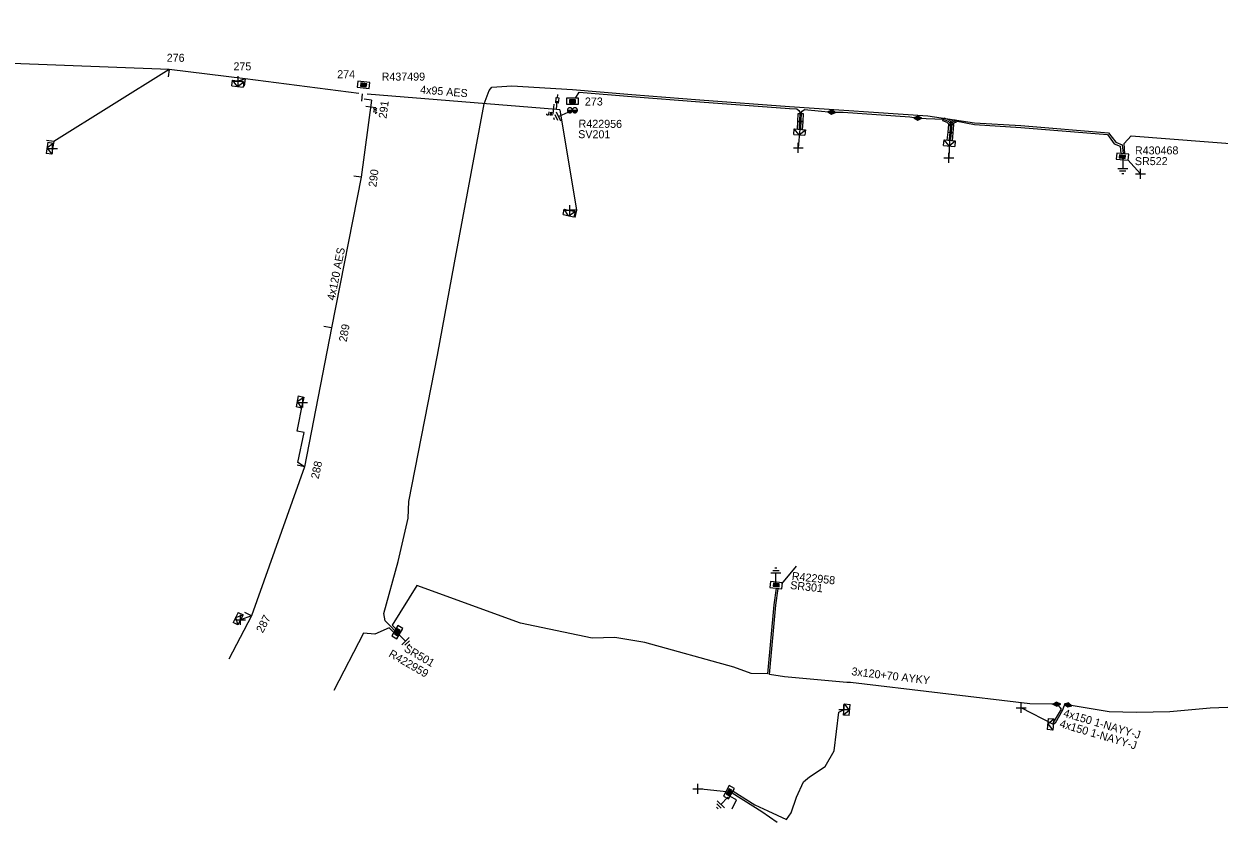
# Model space of a CAD drawing. Extents: x -540247 to -537390, y -1183890 to -1180355.
# Drawn here: x -537955.6 to -537806.3, y -1180715 to -1180615.3 of the extents above; entities that cross this region are included whole.
import ezdxf

# ---------------------------------------------------------------- set-up
doc = ezdxf.new("R2010")
doc.units = 0
for name, color, linetype in [('Vrstva 1', 7, 'Continuous'), ('Vrstva 13', 7, 'Continuous'), ('Vrstva 14', 7, 'Continuous'), ('Vrstva 15', 7, 'Continuous'), ('Vrstva 16', 7, 'Continuous'), ('Vrstva 18', 7, 'Continuous'), ('Vrstva 19', 7, 'Continuous'), ('Vrstva 2', 7, 'Continuous'), ('Vrstva 20', 7, 'Continuous'), ('Vrstva 28', 7, 'Continuous'), ('Vrstva 29', 7, 'Continuous'), ('Vrstva 30', 7, 'Continuous'), ('Vrstva 31', 7, 'Continuous'), ('Vrstva 34', 7, 'Continuous'), ('Vrstva 4', 7, 'Continuous'), ('Vrstva 5', 7, 'Continuous'), ('Vrstva 50', 7, 'Continuous'), ('Vrstva 51', 7, 'Continuous'), ('Vrstva 52', 7, 'Continuous'), ('Vrstva 54', 7, 'Continuous'), ('Vrstva 59', 7, 'Continuous'), ('Vrstva 6', 7, 'Continuous'), ('Vrstva 8', 7, 'Continuous'), ('Vrstva 9', 7, 'Continuous')]:
    doc.layers.add(name, color=color, linetype=linetype)

# ---------------------------------------------------------------- blocks, each defined once
blk = doc.blocks.new('NN450')
at = {"layer": 'Vrstva 2'}
for points in [[(0, 0), (0, 0.07), (-0.01, 0.13), (-0.03, 0.19), (-0.05, 0.25), (-0.08, 0.31), (-0.12, 0.37), (-0.16, 0.42), (-0.21, 0.46), (-0.26, 0.51), (-0.31, 0.54), (-0.37, 0.57), (-0.43, 0.59), (-0.5, 0.61), (-0.56, 0.62), (-0.63, 0.62), (-0.69, 0.62), (-0.75, 0.61), (-0.82, 0.59), (-0.88, 0.57), (-0.94, 0.54), (-0.99, 0.51), (-1.04, 0.46), (-1.09, 0.42), (-1.13, 0.37), (-1.17, 0.31), (-1.2, 0.25), (-1.22, 0.19), (-1.24, 0.13), (-1.25, 0.07), (-1.25, 0), (-1.25, -0.07), (-1.24, -0.13), (-1.22, -0.19), (-1.2, -0.25), (-1.17, -0.31), (-1.13, -0.37), (-1.09, -0.42), (-1.04, -0.46), (-0.99, -0.51), (-0.94, -0.54), (-0.88, -0.57), (-0.82, -0.59), (-0.75, -0.61), (-0.69, -0.62), (-0.62, -0.63), (-0.56, -0.62), (-0.5, -0.61), (-0.43, -0.59), (-0.37, -0.57), (-0.31, -0.54), (-0.26, -0.51), (-0.21, -0.46), (-0.16, -0.42), (-0.12, -0.37), (-0.08, -0.31), (-0.05, -0.25), (-0.03, -0.19), (-0.01, -0.13), (0, -0.07), (0, 0)], [(1.25, 0), (1.25, 0.07), (1.24, 0.13), (1.22, 0.19), (1.2, 0.25), (1.17, 0.31), (1.13, 0.37), (1.09, 0.42), (1.04, 0.46), (0.99, 0.51), (0.94, 0.54), (0.88, 0.57), (0.82, 0.59), (0.75, 0.61), (0.69, 0.62), (0.62, 0.62), (0.56, 0.62), (0.5, 0.61), (0.43, 0.59), (0.37, 0.57), (0.31, 0.54), (0.26, 0.51), (0.21, 0.46), (0.16, 0.42), (0.12, 0.37), (0.08, 0.31), (0.05, 0.25), (0.03, 0.19), (0.01, 0.13), (0, 0.07), (0, 0), (0, -0.07), (0.01, -0.13), (0.03, -0.19), (0.05, -0.25), (0.08, -0.31), (0.12, -0.37), (0.16, -0.42), (0.21, -0.46), (0.26, -0.51), (0.31, -0.54), (0.37, -0.57), (0.43, -0.59), (0.5, -0.61), (0.56, -0.62), (0.63, -0.63), (0.69, -0.62), (0.75, -0.61), (0.82, -0.59), (0.88, -0.57), (0.94, -0.54), (0.99, -0.51), (1.04, -0.46), (1.09, -0.42), (1.13, -0.37), (1.17, -0.31), (1.2, -0.25), (1.22, -0.19), (1.24, -0.13), (1.25, -0.07), (1.25, 0)], [(-1.25, 0), (1.25, 0)], [(-1.23, -0.16), (-0.02, -0.16)], [(-1.16, -0.32), (-0.09, -0.32)], [(-1.03, -0.47), (-0.22, -0.47)], [(0.02, -0.16), (1.23, -0.16)], [(0.09, -0.32), (1.16, -0.32)], [(0.22, -0.47), (1.03, -0.47)]]:
    blk.add_lwpolyline(points, dxfattribs=at)
blk = doc.blocks.new('NN840')
at = {"layer": 'Vrstva 15'}
for points in [[(0, 0.62), (0, -0.63)], [(-0.75, -0.71), (-0.75, -0.66)], [(-0.73, -0.76), (-0.75, -0.71)], [(-0.66, -0.8), (-0.73, -0.76)], [(-0.63, -0.8), (-0.66, -0.8)], [(-0.56, -0.76), (-0.63, -0.8)], [(-0.54, -0.71), (-0.56, -0.76)], [(-0.54, -0.38), (-0.54, -0.71)], [(-0.33, -0.38), (-0.33, -0.8)], [(-0.33, -0.64), (-0.13, -0.38)], [(-0.26, -0.56), (-0.09, -0.8)]]:
    blk.add_lwpolyline(points, dxfattribs=at)
blk = doc.blocks.new('NN870')
at = {"layer": 'Vrstva 4'}
for points in [[(0, -0.25), (0.5, 0), (0, 0.25), (-0.5, 0), (0, -0.25)], [(0.37, 0), (0, 0.19), (-0.36, 0), (0, -0.19), (0.37, 0)], [(0.24, 0), (0, 0.12), (-0.25, 0), (0, -0.12), (0.24, 0)], [(0.12, 0), (0, 0.06), (-0.13, 0), (0, -0.06), (0.12, 0)]]:
    blk.add_lwpolyline(points, dxfattribs=at)
blk = doc.blocks.new('NN800')
at = {"layer": 'Vrstva 1'}
for points in [[(-0.44, 0.44), (0.44, -0.44)], [(-0.44, -0.44), (0.44, 0.44)]]:
    blk.add_lwpolyline(points, dxfattribs=at)
blk = doc.blocks.new('NN820')
at = {"layer": 'Vrstva 13'}
for points in [[(0, 0), (0, -1.05)], [(-0.16, -0.81), (0.16, -0.81)], [(-0.16, -1.47), (-0.16, -0.81)], [(0.16, -1.47), (-0.16, -1.47)], [(0, -1.05), (-0.06, -0.93)], [(0, -1.05), (0.06, -0.93)], [(0, -1.47), (0, -1.87)], [(0.16, -0.81), (0.16, -1.47)]]:
    blk.add_lwpolyline(points, dxfattribs=at)
blk = doc.blocks.new('NN620')
at = {"layer": 'Vrstva 8'}
for points in [[(0.75, 0), (-0.75, 0)], [(-0.75, 0), (-0.75, -0.75)], [(0.75, -0.75), (0.75, 0)], [(-0.75, -0.75), (0.75, -0.75)], [(0.37, -0.18), (-0.38, -0.18)], [(-0.38, -0.18), (-0.38, -0.56)], [(-0.38, -0.56), (0.37, -0.56)], [(0.32, -0.23), (-0.33, -0.23)], [(-0.33, -0.23), (-0.33, -0.51)], [(-0.33, -0.51), (0.32, -0.51)], [(0.27, -0.27), (-0.28, -0.27)], [(-0.28, -0.27), (-0.28, -0.46)], [(-0.28, -0.46), (0.27, -0.46)], [(0.23, -0.32), (-0.23, -0.32)], [(-0.23, -0.32), (-0.23, -0.42)], [(-0.23, -0.42), (0.23, -0.42)], [(-0.19, -0.37), (0.19, -0.37)], [(0.23, -0.42), (0.23, -0.32)], [(0.27, -0.46), (0.27, -0.27)], [(0.32, -0.51), (0.32, -0.23)], [(0.37, -0.56), (0.37, -0.18)]]:
    blk.add_lwpolyline(points, dxfattribs=at)
blk = doc.blocks.new('NN630')
at = {"layer": 'Vrstva 9'}
for points in [[(0, -0.7), (-0.7, 0)], [(-0.7, -0.7), (-0.7, 0), (0.7, 0), (0.7, -0.7)], [(-0.7, -0.7), (0.7, -0.7)], [(0, -0.7), (0.7, 0)]]:
    blk.add_lwpolyline(points, dxfattribs=at)
blk = doc.blocks.new('NN810')
at = {"layer": 'Vrstva 14'}
for points in [[(0, -0.64), (0, -1.89)], [(0.63, -1.89), (-0.62, -1.89)], [(0.39, -2.2), (-0.4, -2.2)], [(0, -2.52), (-0.12, -2.52)], [(0.14, -2.52), (0, -2.52)]]:
    blk.add_lwpolyline(points, dxfattribs=at)
blk = doc.blocks.new('NN510')
at = {"layer": 'Vrstva 2'}
blk.add_lwpolyline([(0, 0), (0, 0.94)], dxfattribs=at)

msp = doc.modelspace()

# ---------------------------------------------------------------- linework, layer by layer
at = {"layer": 'Vrstva 20'}
for points in [[(-537858.98, -1180628.43), (-537858.9, -1180627.46), (-537858.3, -1180627.5), (-537858.38, -1180628.47)], [(-537858.26, -1180626.48), (-537858.3, -1180627.49), (-537858.9, -1180627.47), (-537858.86, -1180626.46)], [(-537840.67, -1180627), (-537840.01, -1180627.26), (-537839.61, -1180627.72), (-537839.91, -1180627.98), (-537840.25, -1180627.6), (-537840.81, -1180627.38)], [(-537839.15, -1180627.57), (-537839.42, -1180627.7), (-537839.59, -1180627.96), (-537839.93, -1180627.74), (-537839.68, -1180627.38), (-537839.31, -1180627.21)], [(-537840.25, -1180629.8), (-537840.13, -1180628.82), (-537839.53, -1180628.9), (-537839.65, -1180629.88)], [(-537840.13, -1180628.84), (-537840.06, -1180627.83), (-537839.46, -1180627.87), (-537839.53, -1180628.88)]]:
    msp.add_lwpolyline(points, close=True, dxfattribs=at)
at = {"layer": 'Vrstva 5'}
for points in [[(-537909.31, -1180691.06), (-537909.75, -1180690.63), (-537910.51, -1180689.86), (-537910.64, -1180688.94), (-537908.88, -1180682.44), (-537907.61, -1180677.05), (-537907.55, -1180674.95), (-537903.95, -1180656.66), (-537901.81, -1180645.14), (-537898.14, -1180625.27), (-537897.51, -1180623.62), (-537897.15, -1180623.19), (-537894.65, -1180623.04), (-537887.06, -1180623.47), (-537879.68, -1180624.11), (-537871.16, -1180624.78), (-537859.96, -1180625.61), (-537842.69, -1180626.79), (-537836.84, -1180627.63), (-537831.04, -1180627.98), (-537820.1, -1180628.88), (-537819.2, -1180630.08), (-537818.39, -1180630.39), (-537818.28, -1180631.48)], [(-537886.7, -1180624.58), (-537886.26, -1180623.81), (-537879.7, -1180624.35), (-537871.18, -1180625.04), (-537859.98, -1180625.86), (-537859.05, -1180625.91), (-537858.81, -1180626.12), (-537858.66, -1180626.33), (-537858.7, -1180627.47), (-537858.76, -1180628.24), (-537858.68, -1180628.45)], [(-537858.68, -1180628.45), (-537858.56, -1180628.26), (-537858.5, -1180627.49), (-537858.46, -1180626.31), (-537858.37, -1180626.17), (-537858.1, -1180625.97), (-537854.69, -1180626.3)], [(-537854.69, -1180626.3), (-537853.24, -1180626.32), (-537844.92, -1180626.88), (-537843.93, -1180627.05)], [(-537843.93, -1180627.05), (-537840.74, -1180627.19), (-537840.13, -1180627.43), (-537839.85, -1180627.74), (-537839.92, -1180628.86), (-537840.02, -1180629.63), (-537839.95, -1180629.84)], [(-537839.95, -1180629.84), (-537839.82, -1180629.65), (-537839.72, -1180628.87), (-537839.65, -1180627.69), (-537839.55, -1180627.54), (-537839.23, -1180627.39), (-537836.86, -1180627.87), (-537831.06, -1180628.23), (-537820.24, -1180629.12), (-537819.38, -1180630.27), (-537818.62, -1180630.58), (-537818.56, -1180631.46)], [(-537818.04, -1180631.5), (-537818.12, -1180630.22), (-537817.28, -1180629.26), (-537797.92, -1180630.76), (-537794.16, -1180631.22), (-537790.18, -1180631.86), (-537788.96, -1180632.47), (-537787.17, -1180640.3), (-537782.56, -1180659.43), (-537787.39, -1180660.39), (-537788.61, -1180660.5), (-537789.99, -1180660.28)], [(-537861.63, -1180685.8), (-537861.91, -1180687.88), (-537862.72, -1180696.48), (-537864.74, -1180696.44), (-537866.92, -1180695.66), (-537878.04, -1180692.58), (-537881.77, -1180691.97), (-537884.64, -1180692.02), (-537893.59, -1180690.16), (-537906.52, -1180685.46), (-537909.62, -1180690.41), (-537909.18, -1180690.84)], [(-537826.57, -1180700.29), (-537827.18, -1180700.3), (-537829.92, -1180700.24), (-537852.35, -1180697.59), (-537852.79, -1180697.56), (-537860.57, -1180696.88), (-537862.47, -1180696.57), (-537861.67, -1180687.9), (-537861.38, -1180685.83)], [(-537909.44, -1180691.29), (-537909.99, -1180690.74), (-537911.8, -1180691.54), (-537913.18, -1180691.42), (-537916.89, -1180698.58)], [(-537779.15, -1180701.57), (-537779, -1180701.54), (-537779.4, -1180699.55), (-537779.5, -1180698.39), (-537780.16, -1180696.25), (-537787.04, -1180698.11), (-537791.79, -1180699.52), (-537804.08, -1180700.65), (-537807.4, -1180700.78), (-537812.42, -1180701.23), (-537816.61, -1180701.32), (-537820.02, -1180701.24), (-537824.76, -1180700.45), (-537825.15, -1180700.38)], [(-537825.15, -1180700.38), (-537825.68, -1180700.51), (-537825.83, -1180701.03), (-537826.78, -1180702.66), (-537826.99, -1180702.82), (-537826.96, -1180702.56), (-537825.98, -1180700.89), (-537826.13, -1180700.68), (-537826.57, -1180700.29)], [(-537867.11, -1180713.35), (-537866.59, -1180712.23), (-537867.39, -1180711.83)], [(-537867.13, -1180711.36), (-537863.43, -1180713.67), (-537861.52, -1180715.01)]]:
    msp.add_lwpolyline(points, dxfattribs=at)
at = {"layer": 'Vrstva 50'}
for points in [[(-537913.77, -1180623.96), (-537927.98, -1180622.13), (-537937.49, -1180620.97), (-537964.79, -1180619.93), (-538007.53, -1180631.08), (-538047.93, -1180634.94), (-538069.97, -1180615.28)], [(-537888.66, -1180626.01), (-537889.08, -1180625.97), (-537912.73, -1180624.06)], [(-537912.19, -1180624.81), (-537913.48, -1180634.44), (-537917.21, -1180653.27), (-537920.56, -1180670.62), (-537927.21, -1180689.24), (-537930.03, -1180694.67)]]:
    msp.add_lwpolyline(points, dxfattribs=at)
at = {"layer": 'Vrstva 52'}
msp.add_lwpolyline([(-537867.01, -1180711.14), (-537864.28, -1180712.85), (-537862.67, -1180713.6), (-537860.35, -1180714.7), (-537859.77, -1180713.84), (-537859.08, -1180711.89), (-537858.21, -1180709.98), (-537857.45, -1180709.34), (-537855.5, -1180708.05), (-537854.39, -1180706.1), (-537853.81, -1180701.3), (-537853.21, -1180700.99), (-537853.16, -1180700.95)], dxfattribs=at)
at = {"layer": 'Vrstva 54'}
for points in [[(-537927.98, -1180622.13), (-537928.86, -1180622.42)], [(-537920.56, -1180670.62), (-537921.39, -1180670.09), (-537920.6, -1180666.34), (-537921.48, -1180666.16), (-537920.8, -1180662.59)], [(-537927.21, -1180689.24), (-537928.56, -1180689.76)]]:
    msp.add_lwpolyline(points, dxfattribs=at)
at = {"layer": 'Vrstva 59'}
for points in [[(-537858.68, -1180628.45), (-537858.86, -1180630.78)], [(-537839.95, -1180629.84), (-537840.06, -1180632)], [(-537817.66, -1180632.25), (-537816.09, -1180634.01)], [(-537860.93, -1180685.24), (-537859.09, -1180683.05)], [(-537826.99, -1180702.82), (-537831.01, -1180700.73)], [(-537867.82, -1180711.22), (-537871.41, -1180710.85)]]:
    msp.add_lwpolyline(points, dxfattribs=at)
at = {"layer": 'Vrstva 8'}
for points in [[(-537937.49, -1180620.97), (-537951.89, -1180629.96), (-537952.06, -1180630.86)], [(-537888.66, -1180626.01), (-537886.57, -1180638.54), (-537887.43, -1180638.57)]]:
    msp.add_lwpolyline(points, dxfattribs=at)

# ---------------------------------------------------------------- block references
at = {"layer": 'Vrstva 13'}
for p, rotation in [((-537937.49, -1180620.97), 172.75510552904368), ((-537927.98, -1180622.13), 172.75510566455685), ((-537913.35, -1180624.01), 172.75510566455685), ((-537912.18, -1180624.81), 82.40180553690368), ((-537951.89, -1180629.96), 82.7499055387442), ((-537913.48, -1180634.44), 82.40180553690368), ((-537886.57, -1180638.54), 167.82687492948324), ((-537917.21, -1180653.27), 79.96978614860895), ((-537920.56, -1180670.62), 78.16397224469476), ((-537927.21, -1180689.24), 62.55184721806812)]:
    msp.add_blockref('NN510', p, dxfattribs=dict(at, rotation=rotation))
at = {"layer": 'Vrstva 13', "xscale": 0.5, "yscale": 0.5}
msp.add_blockref('NN450', (-537887.09, -1180626.07), dxfattribs=at)
at = {"layer": 'Vrstva 15'}
for p, rotation in [((-537887.09, -1180626.07), -65.18650837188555), ((-537861.67, -1180685.77), 180), ((-537909.29, -1180691.08), 45), ((-537867.21, -1180711.46), -45)]:
    msp.add_blockref('NN810', p, dxfattribs=dict(at, rotation=rotation))
msp.add_blockref('NN810', (-537818.32, -1180631.5), dxfattribs=at)
at = {"layer": 'Vrstva 16', "rotation": 175.3789777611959}
msp.add_blockref('NN820', (-537889.08, -1180625.97), dxfattribs=at)
at = {"layer": 'Vrstva 18'}
for p, rotation in [((-537912.3, -1180625.63), 82.34341949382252), ((-537889.48, -1180625.94), -4.621508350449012)]:
    msp.add_blockref('NN840', p, dxfattribs=dict(at, rotation=rotation))
at = {"layer": 'Vrstva 19'}
for p, rotation in [((-537854.69, -1180626.3), 174.47245978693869), ((-537843.93, -1180627.05), -2.5129359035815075), ((-537826.57, -1180700.29), -179.06080897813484), ((-537825.15, -1180700.38), -10.17551077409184)]:
    msp.add_blockref('NN870', p, dxfattribs=dict(at, rotation=rotation))
at = {"layer": 'Vrstva 28'}
for p, rotation in [((-537913.25, -1180623.27), 172.67699996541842), ((-537887.09, -1180625.32), 179.67300004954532), ((-537818.32, -1180631.5), -4.546858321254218), ((-537861.67, -1180685.77), 173.8718276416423), ((-537909.29, -1180691.08), 59.82424448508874), ((-537867.21, -1180711.46), -118.90829165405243)]:
    msp.add_blockref('NN620', p, dxfattribs=dict(at, rotation=rotation))
at = {"layer": 'Vrstva 31'}
for p, rotation in [((-537928.86, -1180622.42), -7.244894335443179), ((-537858.68, -1180628.45), -4.34675545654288), ((-537952.06, -1180630.86), -97.25009446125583), ((-537839.95, -1180629.84), -4.348538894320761), ((-537887.43, -1180638.57), -12.173125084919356), ((-537920.8, -1180662.59), -100.94692228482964), ((-537928.56, -1180689.76), -117.44815278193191), ((-537853.15, -1180700.95), 84.30260002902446), ((-537826.99, -1180702.82), -95.7874176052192)]:
    msp.add_blockref('NN630', p, dxfattribs=dict(at, rotation=rotation))
at = {"layer": 'Vrstva 34'}
for p, rotation in [((-537928.86, -1180622.42), 45.00000009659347), ((-537952.06, -1180630.86), 45), ((-537858.86, -1180630.78), 45), ((-537840.06, -1180632), 45), ((-537816.09, -1180634.01), 45), ((-537887.43, -1180638.57), 45), ((-537920.8, -1180662.59), 45), ((-537928.56, -1180689.76), 45), ((-537853.16, -1180700.95), 45), ((-537831.01, -1180700.73), 45), ((-537871.41, -1180710.85), 45)]:
    msp.add_blockref('NN800', p, dxfattribs=dict(at, rotation=rotation))

# ---------------------------------------------------------------- texts
at = {"layer": 'Vrstva 14'}
for s, p in [('276', (-537937.79, -1180620.02)), ('275', (-537929.45, -1180621.09)), ('274', (-537916.48, -1180622.07)), ('273', (-537885.53, -1180625.48))]:
    msp.add_text(s, height=1, dxfattribs=at).set_placement(p)
for s, rotation, p in [('291', 82.402, (-537910.33, -1180627.15)), ('290', 82.402, (-537911.6, -1180635.73)), ('289', 79.97, (-537915.31, -1180655.08)), ('288', 78.164, (-537918.81, -1180672.2)), ('287', 62.552, (-537925.79, -1180691.46))]:
    msp.add_text(s, height=1, rotation=rotation, dxfattribs=at).set_placement(p)
at = {"layer": 'Vrstva 29'}
for s, p in [('R437499', (-537910.93, -1180622.37)), ('R430468', (-537816.79, -1180631.59))]:
    msp.add_text(s, height=1, dxfattribs=at).set_placement(p)
for s, rotation, p in [('R422956', 359.673, (-537886.32, -1180628.25)), ('R422958', 353.872, (-537859.71, -1180684.74)), ('R422959', 329.824, (-537910.14, -1180694.27))]:
    msp.add_text(s, height=1, rotation=rotation, dxfattribs=at).set_placement(p)
at = {"layer": 'Vrstva 30'}
for s, rotation, p in [('SV201', 359.673, (-537886.37, -1180629.56)), ('SR301', 353.872, (-537859.91, -1180685.88)), ('SR501', 329.824, (-537908.22, -1180693.62))]:
    msp.add_text(s, height=1, rotation=rotation, dxfattribs=at).set_placement(p)
msp.add_text('SR522', height=1, dxfattribs=at).set_placement((-537816.8, -1180632.93))
at = {"layer": 'Vrstva 51'}
for s, rotation, p in [('4x95 AES', 355.379, (-537906.15, -1180623.97)), ('4x120 AES', 78.78, (-537916.8, -1180649.89))]:
    msp.add_text(s, height=1, rotation=rotation, dxfattribs=at).set_placement(p)
at = {"layer": 'Vrstva 6'}
for s, rotation, p in [('3x120+70 AYKY', 353.266, (-537852.26, -1180696.65)), ('4x150 1-NAYY-J', 343.503, (-537825.82, -1180701.81)), ('4x150 1-NAYY-J', 343.503, (-537826.28, -1180703.13))]:
    msp.add_text(s, height=1, rotation=rotation, dxfattribs=at).set_placement(p)

doc.saveas('drawing.dxf')
